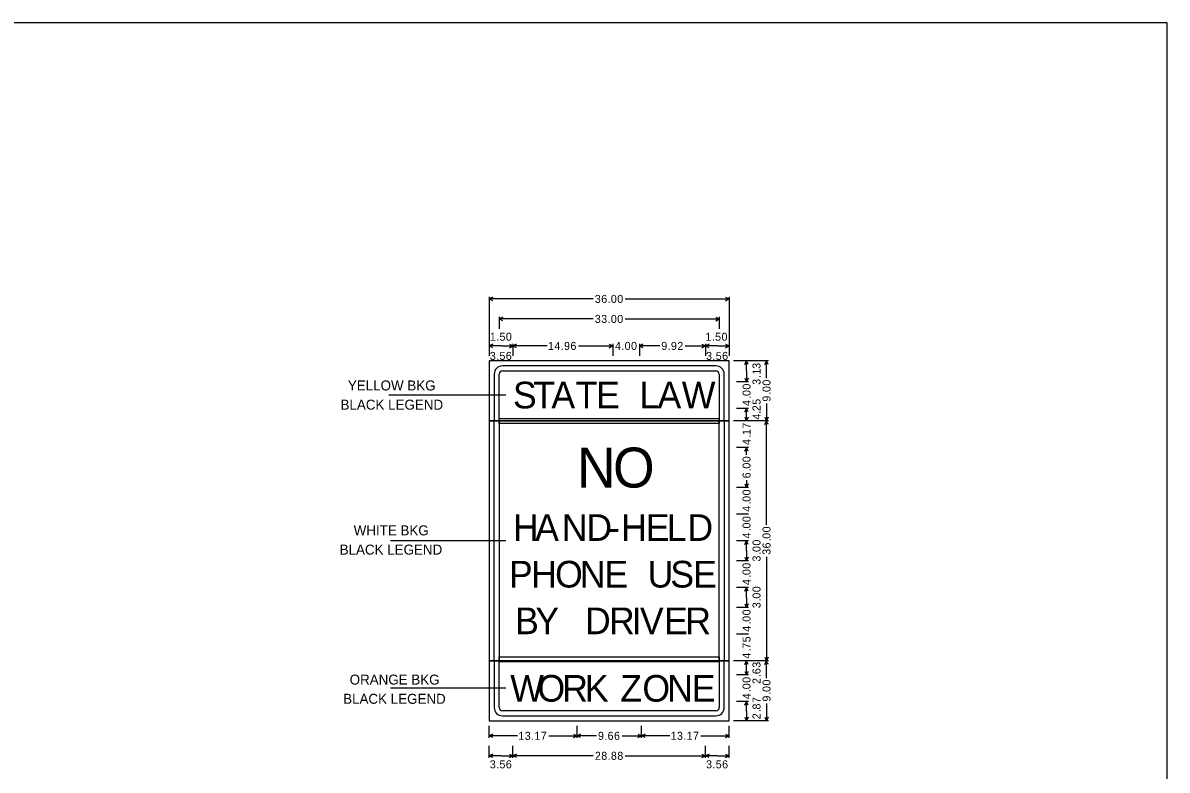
# Model space of a CAD drawing. Extents: x 1806907 to 1812607, y 675071 to 676228.
# Drawn here: x 1807792 to 1808557, y 675571 to 676070 of the extents above; entities that cross this region are included whole.
import ezdxf

# ---------------------------------------------------------------- set-up
doc = ezdxf.new("R2010")
doc.units = 0
for name, color, linetype in [('Default', 7, 'Continuous'), ('DSN_DRFT_Named-Boundary', 7, 'Continuous'), ('R_Draft', 7, 'Continuous')]:
    doc.layers.add(name, color=color, linetype=linetype)

msp = doc.modelspace()

# ---------------------------------------------------------------- linework, layer by layer
at = {"layer": 'Default'}
for p, q in [((1808103.75, 675887.08), (1808103.75, 675850.33)), ((1808106.14, 675886.94), (1808103.75, 675885.75)), ((1808261.73, 675886.94), (1808264.13, 675885.75)), ((1808264.13, 675887.08), (1808264.13, 675850.33)), ((1808173.29, 675885.75), (1808103.75, 675885.75)), ((1808106.14, 675884.55), (1808103.75, 675885.75)), ((1808194.58, 675885.75), (1808264.13, 675885.75)), ((1808261.73, 675884.55), (1808264.13, 675885.75)), ((1808103.75, 675873.72), (1808103.75, 675865.7)), ((1808110.43, 675873.72), (1808110.43, 675865.7)), ((1808112.82, 675873.58), (1808110.43, 675872.38)), ((1808173.29, 675872.38), (1808110.43, 675872.38)), ((1808112.82, 675871.19), (1808110.43, 675872.38)), ((1808194.58, 675872.38), (1808257.44, 675872.38)), ((1808255.05, 675873.58), (1808257.44, 675872.38)), ((1808255.05, 675871.19), (1808257.44, 675872.38)), ((1808257.44, 675873.72), (1808257.44, 675865.7)), ((1808257.44, 675873.72), (1808257.44, 675865.7)), ((1808264.13, 675873.72), (1808264.13, 675865.7)), ((1808103.75, 675855.67), (1808103.75, 675847.65)), ((1808119.61, 675855.67), (1808119.61, 675847.65)), ((1808186.25, 675855.67), (1808186.25, 675847.65)), ((1808204.07, 675855.67), (1808204.07, 675847.65)), ((1808248.27, 675855.67), (1808248.27, 675847.65)), ((1808248.27, 675855.67), (1808248.27, 675847.65)), ((1808264.13, 675855.67), (1808264.13, 675847.65)), ((1808106.14, 675855.53), (1808103.75, 675854.33)), ((1808111.68, 675854.33), (1808103.75, 675854.33)), ((1808106.14, 675853.14), (1808103.75, 675854.33)), ((1808111.68, 675854.33), (1808119.61, 675854.33)), ((1808117.21, 675855.53), (1808119.61, 675854.33)), ((1808117.21, 675853.14), (1808119.61, 675854.33)), ((1808122, 675855.53), (1808119.61, 675854.33)), ((1808142.48, 675854.33), (1808119.61, 675854.33)), ((1808122, 675853.14), (1808119.61, 675854.33)), ((1808163.38, 675854.33), (1808186.25, 675854.33)), ((1808183.86, 675855.53), (1808186.25, 675854.33)), ((1808183.86, 675853.14), (1808186.25, 675854.33)), ((1808206.46, 675855.53), (1808204.07, 675854.33)), ((1808217.67, 675854.33), (1808204.07, 675854.33)), ((1808206.46, 675853.14), (1808204.07, 675854.33)), ((1808234.67, 675854.33), (1808248.27, 675854.33)), ((1808245.87, 675855.53), (1808248.27, 675854.33)), ((1808245.87, 675853.14), (1808248.27, 675854.33)), ((1808250.66, 675855.53), (1808248.27, 675854.33)), ((1808256.2, 675854.33), (1808248.27, 675854.33)), ((1808250.66, 675853.14), (1808248.27, 675854.33)), ((1808256.2, 675854.33), (1808264.13, 675854.33)), ((1808261.73, 675855.53), (1808264.13, 675854.33)), ((1808261.73, 675853.14), (1808264.13, 675854.33)), ((1808264.13, 675844.31), (1808103.75, 675844.31)), ((1808103.75, 675844.31), (1808103.75, 675804.21)), ((1808255.22, 675840.97), (1808112.66, 675840.97)), ((1808264.13, 675804.21), (1808264.13, 675844.31)), ((1808290.36, 675844.31), (1808266.98, 675844.31)), ((1808277, 675844.31), (1808268.98, 675844.31)), ((1808274.47, 675841.92), (1808275.66, 675844.31)), ((1808275.66, 675837.35), (1808275.66, 675844.31)), ((1808276.86, 675841.92), (1808275.66, 675844.31)), ((1808287.83, 675841.92), (1808289.03, 675844.31)), ((1808289.03, 675832.78), (1808289.03, 675844.31)), ((1808290.22, 675841.92), (1808289.03, 675844.31)), ((1808107.09, 675835.4), (1808107.09, 675804.21)), ((1808110.43, 675804.21), (1808110.43, 675835.4)), ((1808112.66, 675837.63), (1808255.22, 675837.63)), ((1808257.44, 675835.4), (1808257.44, 675804.21)), ((1808260.78, 675804.21), (1808260.78, 675835.4)), ((1808274.47, 675832.78), (1808275.66, 675830.39)), ((1808275.66, 675837.35), (1808275.66, 675830.39)), ((1808276.86, 675832.78), (1808275.66, 675830.39)), ((1808277, 675830.39), (1808268.98, 675830.39)), ((1808277, 675812.57), (1808268.98, 675812.57)), ((1808274.47, 675810.18), (1808275.66, 675812.57)), ((1808275.66, 675804.21), (1808275.66, 675812.57)), ((1808276.86, 675810.18), (1808275.66, 675812.57)), ((1808289.03, 675815.74), (1808289.03, 675804.21)), ((1808264.13, 675804.21), (1808103.75, 675804.21)), ((1808103.75, 675804.21), (1808103.75, 675643.83)), ((1808103.75, 675804.21), (1808264.13, 675804.21)), ((1808107.09, 675643.83), (1808107.09, 675804.21)), ((1808107.09, 675804.21), (1808110.43, 675804.21)), ((1808107.09, 675804.21), (1808110.43, 675804.21)), ((1808110.43, 675805.88), (1808257.44, 675805.88)), ((1808110.43, 675802.54), (1808110.43, 675805.88)), ((1808110.43, 675804.21), (1808110.43, 675643.83)), ((1808257.44, 675802.54), (1808110.43, 675802.54)), ((1808257.44, 675805.88), (1808257.44, 675802.54)), ((1808257.44, 675643.83), (1808257.44, 675804.21)), ((1808257.44, 675804.21), (1808260.78, 675804.21)), ((1808257.44, 675804.21), (1808260.78, 675804.21)), ((1808260.78, 675804.21), (1808260.78, 675643.83)), ((1808264.13, 675643.83), (1808264.13, 675804.21)), ((1808290.36, 675804.21), (1808266.98, 675804.21)), ((1808290.36, 675804.21), (1808266.98, 675804.21)), ((1808277, 675804.21), (1808268.98, 675804.21)), ((1808277, 675804.21), (1808268.98, 675804.21)), ((1808274.47, 675806.6), (1808275.66, 675804.21)), ((1808276.86, 675806.6), (1808275.66, 675804.21)), ((1808287.83, 675806.6), (1808289.03, 675804.21)), ((1808287.83, 675801.82), (1808289.03, 675804.21)), ((1808290.22, 675806.6), (1808289.03, 675804.21)), ((1808289.03, 675734.67), (1808289.03, 675804.21)), ((1808290.22, 675801.82), (1808289.03, 675804.21)), ((1808277, 675786.39), (1808268.98, 675786.39)), ((1808274.47, 675784), (1808275.66, 675786.39)), ((1808275.66, 675781.56), (1808275.66, 675786.39)), ((1808276.86, 675784), (1808275.66, 675786.39)), ((1808275.66, 675764.5), (1808275.66, 675759.66)), ((1808277, 675759.66), (1808268.98, 675759.66)), ((1808274.47, 675762.05), (1808275.66, 675759.66)), ((1808276.86, 675762.05), (1808275.66, 675759.66)), ((1808277, 675741.84), (1808268.98, 675741.84)), ((1808277, 675724.02), (1808268.98, 675724.02)), ((1808274.47, 675721.63), (1808275.66, 675724.02)), ((1808275.66, 675717.34), (1808275.66, 675724.02)), ((1808276.86, 675721.63), (1808275.66, 675724.02)), ((1808277, 675710.66), (1808268.98, 675710.66)), ((1808274.47, 675713.05), (1808275.66, 675710.66)), ((1808275.66, 675717.34), (1808275.66, 675710.66)), ((1808276.86, 675713.05), (1808275.66, 675710.66)), ((1808289.03, 675713.38), (1808289.03, 675643.83)), ((1808277, 675692.84), (1808268.98, 675692.84)), ((1808274.47, 675690.45), (1808275.66, 675692.84)), ((1808275.66, 675686.16), (1808275.66, 675692.84)), ((1808276.86, 675690.45), (1808275.66, 675692.84)), ((1808274.47, 675681.86), (1808275.66, 675679.47)), ((1808275.66, 675686.16), (1808275.66, 675679.47)), ((1808276.86, 675681.86), (1808275.66, 675679.47)), ((1808277, 675679.47), (1808268.98, 675679.47)), ((1808277, 675661.65), (1808268.98, 675661.65)), ((1808277, 675661.65), (1808268.98, 675661.65)), ((1808264.13, 675643.83), (1808103.75, 675643.83)), ((1808103.75, 675643.83), (1808103.75, 675603.74)), ((1808103.75, 675643.83), (1808264.13, 675643.83)), ((1808110.43, 675643.83), (1808107.09, 675643.83)), ((1808107.09, 675643.83), (1808107.09, 675612.65)), ((1808110.43, 675643.83), (1808107.09, 675643.83)), ((1808110.43, 675646.62), (1808257.44, 675646.62)), ((1808110.43, 675643.28), (1808110.43, 675646.62)), ((1808110.43, 675612.65), (1808110.43, 675643.83)), ((1808257.44, 675643.28), (1808110.43, 675643.28)), ((1808257.44, 675646.62), (1808257.44, 675643.28)), ((1808260.78, 675643.83), (1808257.44, 675643.83)), ((1808257.44, 675643.83), (1808257.44, 675612.65)), ((1808260.78, 675643.83), (1808257.44, 675643.83)), ((1808260.78, 675612.65), (1808260.78, 675643.83)), ((1808264.13, 675603.74), (1808264.13, 675643.83)), ((1808290.36, 675643.83), (1808266.98, 675643.83)), ((1808290.36, 675643.83), (1808266.98, 675643.83)), ((1808277, 675643.83), (1808268.98, 675643.83)), ((1808277, 675643.83), (1808268.98, 675643.83)), ((1808274.47, 675641.44), (1808275.66, 675643.83)), ((1808275.66, 675634.37), (1808275.66, 675643.83)), ((1808276.86, 675641.44), (1808275.66, 675643.83)), ((1808287.83, 675646.22), (1808289.03, 675643.83)), ((1808287.83, 675641.44), (1808289.03, 675643.83)), ((1808290.22, 675646.22), (1808289.03, 675643.83)), ((1808289.03, 675632.3), (1808289.03, 675643.83)), ((1808290.22, 675641.44), (1808289.03, 675643.83)), ((1808277, 675634.37), (1808268.98, 675634.37)), ((1808274.47, 675636.76), (1808275.66, 675634.37)), ((1808276.86, 675636.76), (1808275.66, 675634.37)), ((1808277, 675616.55), (1808268.98, 675616.55)), ((1808277, 675616.55), (1808268.98, 675616.55)), ((1808274.47, 675614.16), (1808275.66, 675616.55)), ((1808275.66, 675610.14), (1808275.66, 675616.55)), ((1808276.86, 675614.16), (1808275.66, 675616.55)), ((1808289.03, 675615.27), (1808289.03, 675603.74)), ((1808103.75, 675603.74), (1808264.13, 675603.74)), ((1808255.22, 675610.42), (1808112.66, 675610.42)), ((1808112.66, 675607.08), (1808255.22, 675607.08)), ((1808290.36, 675603.74), (1808266.98, 675603.74)), ((1808277, 675603.74), (1808268.98, 675603.74)), ((1808274.47, 675606.13), (1808275.66, 675603.74)), ((1808275.66, 675610.14), (1808275.66, 675603.74)), ((1808276.86, 675606.13), (1808275.66, 675603.74)), ((1808287.83, 675606.13), (1808289.03, 675603.74)), ((1808290.22, 675606.13), (1808289.03, 675603.74)), ((1808103.75, 675592.38), (1808103.75, 675600.4)), ((1808162.42, 675592.38), (1808162.42, 675600.4)), ((1808205.45, 675592.38), (1808205.45, 675600.4)), ((1808205.45, 675592.38), (1808205.45, 675600.4)), ((1808264.13, 675592.38), (1808264.13, 675600.4)), ((1808106.14, 675594.91), (1808103.75, 675593.71)), ((1808122.68, 675593.71), (1808103.75, 675593.71)), ((1808106.14, 675592.52), (1808103.75, 675593.71)), ((1808143.49, 675593.71), (1808162.42, 675593.71)), ((1808160.03, 675594.91), (1808162.42, 675593.71)), ((1808160.03, 675592.52), (1808162.42, 675593.71)), ((1808164.81, 675594.91), (1808162.42, 675593.71)), ((1808175.38, 675593.71), (1808162.42, 675593.71)), ((1808164.81, 675592.52), (1808162.42, 675593.71)), ((1808192.49, 675593.71), (1808205.45, 675593.71)), ((1808203.06, 675594.91), (1808205.45, 675593.71)), ((1808203.06, 675592.52), (1808205.45, 675593.71)), ((1808207.84, 675594.91), (1808205.45, 675593.71)), ((1808224.38, 675593.71), (1808205.45, 675593.71)), ((1808207.84, 675592.52), (1808205.45, 675593.71)), ((1808245.19, 675593.71), (1808264.13, 675593.71)), ((1808261.73, 675594.91), (1808264.13, 675593.71)), ((1808261.73, 675592.52), (1808264.13, 675593.71)), ((1808103.75, 675579.01), (1808103.75, 675587.03)), ((1808106.14, 675581.54), (1808103.75, 675580.35)), ((1808111.68, 675580.35), (1808103.75, 675580.35)), ((1808106.14, 675579.15), (1808103.75, 675580.35)), ((1808111.68, 675580.35), (1808119.61, 675580.35)), ((1808117.21, 675581.54), (1808119.61, 675580.35)), ((1808117.21, 675579.15), (1808119.61, 675580.35)), ((1808119.61, 675579.01), (1808119.61, 675587.03)), ((1808122, 675581.54), (1808119.61, 675580.35)), ((1808173.22, 675580.35), (1808119.61, 675580.35)), ((1808122, 675579.15), (1808119.61, 675580.35)), ((1808194.65, 675580.35), (1808248.27, 675580.35)), ((1808245.87, 675581.54), (1808248.27, 675580.35)), ((1808245.87, 675579.15), (1808248.27, 675580.35)), ((1808248.27, 675579.01), (1808248.27, 675587.03)), ((1808248.27, 675579.01), (1808248.27, 675587.03)), ((1808250.66, 675581.54), (1808248.27, 675580.35)), ((1808256.2, 675580.35), (1808248.27, 675580.35)), ((1808250.66, 675579.15), (1808248.27, 675580.35)), ((1808256.2, 675580.35), (1808264.13, 675580.35)), ((1808261.73, 675581.54), (1808264.13, 675580.35)), ((1808261.73, 675579.15), (1808264.13, 675580.35)), ((1808264.13, 675579.01), (1808264.13, 675587.03))]:
    msp.add_line(p, q, dxfattribs=at)
for centre, radius, start, end in [((1808112.66, 675835.4), 5.57, 90, 180.00001), ((1808255.22, 675835.4), 5.57, 0.00001, 90), ((1808112.66, 675835.4), 2.23, 90, 180.00001), ((1808255.22, 675835.4), 2.23, 0.00001, 90), ((1808112.66, 675612.65), 5.57, 180.00001, 270), ((1808112.66, 675612.65), 2.23, 180.00001, 270), ((1808255.22, 675612.65), 5.57, 270, 0.00001), ((1808255.22, 675612.65), 2.23, 270, 0.00001)]:
    msp.add_arc(centre, radius, start, end, dxfattribs=at)
at = {"layer": 'DSN_DRFT_Named-Boundary'}
msp.add_lwpolyline([(1806906.68, 675071.2), (1808556.68, 675071.2), (1808556.68, 676070.26), (1806906.68, 676070.26)], close=True, dxfattribs=at)
at = {"layer": 'R_Draft'}
for p, q in [((1808114.89, 675821.48), (1808036.71, 675821.48)), ((1808114.89, 675724.02), (1808037.88, 675724.02)), ((1808114.89, 675625.46), (1808037.88, 675625.46))]:
    msp.add_line(p, q, dxfattribs=at)

# ---------------------------------------------------------------- texts
at = {"layer": 'Default'}
for s, height, p in [('3', 5.35, (1808174.29, 675883.07)), ('6', 5.35, (1808178.58, 675883.07)), ('0', 5.35, (1808185.01, 675883.07)), ('0', 5.35, (1808189.3, 675883.07)), ('.', 5.35, (1808182.86, 675883.07)), ('3', 5.35, (1808174.29, 675869.71)), ('3', 5.35, (1808178.58, 675869.71)), ('0', 5.35, (1808185.01, 675869.71)), ('0', 5.35, (1808189.3, 675869.71)), ('0', 5.35, (1808114.88, 675857.8)), ('.', 5.35, (1808182.86, 675869.71)), ('0', 5.35, (1808258.95, 675857.8)), ('1', 5.35, (1808104.16, 675857.8)), ('.', 5.35, (1808108.44, 675857.8)), ('5', 5.35, (1808110.6, 675857.8)), ('1', 5.35, (1808143.01, 675851.66)), ('4', 5.35, (1808147.29, 675851.66)), ('9', 5.35, (1808153.73, 675851.66)), ('6', 5.35, (1808158.01, 675851.66)), ('4', 5.35, (1808187.79, 675851.66)), ('0', 5.35, (1808194.22, 675851.66)), ('0', 5.35, (1808198.51, 675851.66)), ('9', 5.35, (1808218.7, 675851.66)), ('9', 5.35, (1808225.13, 675851.66)), ('2', 5.35, (1808229.42, 675851.66)), ('1', 5.35, (1808248.23, 675857.8)), ('.', 5.35, (1808252.52, 675857.8)), ('5', 5.35, (1808254.67, 675857.8)), ('3', 5.35, (1808104.13, 675844.98)), ('5', 5.35, (1808110.57, 675844.98)), ('6', 5.35, (1808114.85, 675844.98)), ('.', 5.35, (1808151.57, 675851.66)), ('.', 5.35, (1808192.07, 675851.66)), ('.', 5.35, (1808222.98, 675851.66)), ('3', 5.35, (1808248.65, 675844.98)), ('5', 5.35, (1808255.09, 675844.98)), ('6', 5.35, (1808259.37, 675844.98)), ('.', 5.35, (1808108.41, 675844.98)), ('.', 5.35, (1808252.93, 675844.98)), ('S', 17.82, (1808119.61, 675812.57)), ('T', 17.82, (1808133.15, 675812.57)), ('A', 17.82, (1808145.27, 675812.57)), ('T', 17.82, (1808161.48, 675812.57)), ('E', 17.82, (1808175.2, 675812.57)), ('L', 17.82, (1808204.07, 675812.57)), ('A', 17.82, (1808216.19, 675812.57)), ('W', 17.82, (1808232.41, 675812.57)), ('O', 26.73, (1808186.47, 675759.66)), ('N', 26.73, (1808162.42, 675759.66)), ('H', 17.82, (1808119.61, 675724.02)), ('A', 17.82, (1808134.4, 675724.02)), ('N', 17.82, (1808152.22, 675724.02)), ('D', 17.82, (1808168.61, 675724.02)), ('H', 17.82, (1808191.95, 675724.02)), ('E', 17.82, (1808208.35, 675724.02)), ('L', 17.82, (1808222.43, 675724.02)), ('D', 17.82, (1808236.15, 675724.02)), ('-', 17.82, (1808183.04, 675724.02)), ('P', 17.82, (1808116.93, 675692.84)), ('H', 17.82, (1808131.72, 675692.84)), ('O', 17.82, (1808147.76, 675692.84)), ('N', 17.82, (1808164.33, 675692.84)), ('E', 17.82, (1808180.73, 675692.84)), ('U', 17.82, (1808209.6, 675692.84)), ('S', 17.82, (1808224.74, 675692.84)), ('E', 17.82, (1808239.89, 675692.84)), ('B', 17.82, (1808121.03, 675661.65)), ('Y', 17.82, (1808134.57, 675661.65)), ('D', 17.82, (1808167.72, 675661.65)), ('R', 17.82, (1808183.76, 675661.65)), ('I', 17.82, (1808198.9, 675661.65)), ('V', 17.82, (1808204.43, 675661.65)), ('E', 17.82, (1808220.64, 675661.65)), ('R', 17.82, (1808234.72, 675661.65)), ('W', 17.82, (1808117.78, 675616.55)), ('O', 17.82, (1808135.96, 675616.55)), ('R', 17.82, (1808152.53, 675616.55)), ('K', 17.82, (1808167.67, 675616.55)), ('Z', 17.82, (1808191.29, 675616.55)), ('O', 17.82, (1808206.08, 675616.55)), ('N', 17.82, (1808222.65, 675616.55)), ('E', 17.82, (1808239.04, 675616.55)), ('1', 5.35, (1808123.2, 675591.04)), ('3', 5.35, (1808127.48, 675591.04)), ('1', 5.35, (1808133.92, 675591.04)), ('7', 5.35, (1808138.2, 675591.04)), ('9', 5.35, (1808176.41, 675591.04)), ('6', 5.35, (1808182.84, 675591.04)), ('6', 5.35, (1808187.13, 675591.04)), ('1', 5.35, (1808224.91, 675591.04)), ('3', 5.35, (1808229.19, 675591.04)), ('1', 5.35, (1808235.63, 675591.04)), ('7', 5.35, (1808239.91, 675591.04)), ('.', 5.35, (1808131.77, 675591.04)), ('.', 5.35, (1808180.69, 675591.04)), ('.', 5.35, (1808233.47, 675591.04)), ('2', 5.35, (1808174.33, 675577.68)), ('8', 5.35, (1808178.62, 675577.68)), ('8', 5.35, (1808185.05, 675577.68)), ('8', 5.35, (1808189.34, 675577.68)), ('3', 5.35, (1808104.13, 675571.99)), ('.', 5.35, (1808108.41, 675571.99)), ('5', 5.35, (1808110.57, 675571.99)), ('6', 5.35, (1808114.85, 675571.99)), ('.', 5.35, (1808182.9, 675577.68)), ('3', 5.35, (1808248.65, 675571.99)), ('.', 5.35, (1808252.93, 675571.99)), ('5', 5.35, (1808255.09, 675571.99)), ('6', 5.35, (1808259.37, 675571.99))]:
    msp.add_text(s, height=height, dxfattribs=at).set_placement(p)
for s, p in [('3', (1808285.02, 675839.02)), ('1', (1808285.02, 675835.21)), ('.', (1808285.02, 675832.94)), ('0', (1808278.34, 675825.13)), ('3', (1808285.02, 675828.3)), ('0', (1808291.7, 675827.8)), ('0', (1808291.7, 675823.52)), ('0', (1808278.34, 675820.85)), ('4', (1808278.34, 675814.18)), ('.', (1808278.34, 675819.08)), ('5', (1808285.02, 675814.99)), ('9', (1808291.7, 675817.08)), ('.', (1808291.7, 675821.76)), ('2', (1808285.02, 675810.71)), ('.', (1808285.02, 675808.94)), ('7', (1808278.34, 675799.04)), ('4', (1808285.02, 675805.14)), ('1', (1808278.34, 675794.75)), ('4', (1808278.34, 675788.09)), ('.', (1808278.34, 675792.99)), ('0', (1808278.34, 675776.58)), ('0', (1808278.34, 675772.3)), ('.', (1808278.34, 675770.54)), ('6', (1808278.34, 675765.83)), ('0', (1808278.34, 675754.41)), ('0', (1808278.34, 675750.12)), ('.', (1808278.34, 675748.36)), ('4', (1808278.34, 675743.46)), ('0', (1808278.34, 675736.59)), ('0', (1808278.34, 675732.3)), ('0', (1808291.7, 675729.69)), ('4', (1808278.34, 675725.64)), ('.', (1808278.34, 675730.54)), ('0', (1808291.7, 675725.41)), ('0', (1808285.02, 675720.87)), ('0', (1808285.02, 675716.58)), ('6', (1808291.7, 675718.94)), ('3', (1808291.7, 675714.72)), ('.', (1808291.7, 675723.65)), ('3', (1808285.02, 675710.18)), ('.', (1808285.02, 675714.82)), ('0', (1808278.34, 675705.4)), ('0', (1808278.34, 675701.12)), ('4', (1808278.34, 675694.46)), ('.', (1808278.34, 675699.35)), ('0', (1808285.02, 675689.68)), ('0', (1808285.02, 675685.4)), ('3', (1808285.02, 675678.99)), ('.', (1808285.02, 675683.64)), ('0', (1808278.34, 675674.22)), ('0', (1808278.34, 675669.93)), ('4', (1808278.34, 675663.27)), ('.', (1808278.34, 675668.17)), ('5', (1808278.34, 675656.2)), ('7', (1808278.34, 675651.92)), ('.', (1808278.34, 675650.16)), ('4', (1808278.34, 675645.26)), ('3', (1808285.02, 675639.19)), ('6', (1808285.02, 675634.91)), ('.', (1808285.02, 675633.14)), ('0', (1808278.34, 675629.11)), ('0', (1808278.34, 675624.83)), ('2', (1808285.02, 675628.38)), ('0', (1808291.7, 675627.33)), ('0', (1808291.7, 675623.04)), ('4', (1808278.34, 675618.16)), ('.', (1808278.34, 675623.06)), ('7', (1808285.02, 675615.62)), ('9', (1808291.7, 675616.61)), ('.', (1808291.7, 675621.28)), ('8', (1808285.02, 675611.29)), ('2', (1808285.02, 675604.79)), ('.', (1808285.02, 675609.55))]:
    msp.add_text(s, height=5.35, rotation=90, dxfattribs=at).set_placement(p)
at = {"layer": 'R_Draft'}
for s, height, p in [('YELLOW BKG', 6.682, (1808009.32, 675824.56)), ('BLACK LEGEND', 6.6825, (1808004.41, 675811.71)), ('WHITE BKG', 6.682, (1808013.2, 675727.69)), ('BLACK LEGEND', 6.6825, (1808003.83, 675714.84)), ('ORANGE BKG', 6.682, (1808010.51, 675627.96)), ('BLACK LEGEND', 6.6825, (1808006.16, 675615.11))]:
    msp.add_text(s, height=height, dxfattribs=at).set_placement(p)

doc.saveas('drawing.dxf')
